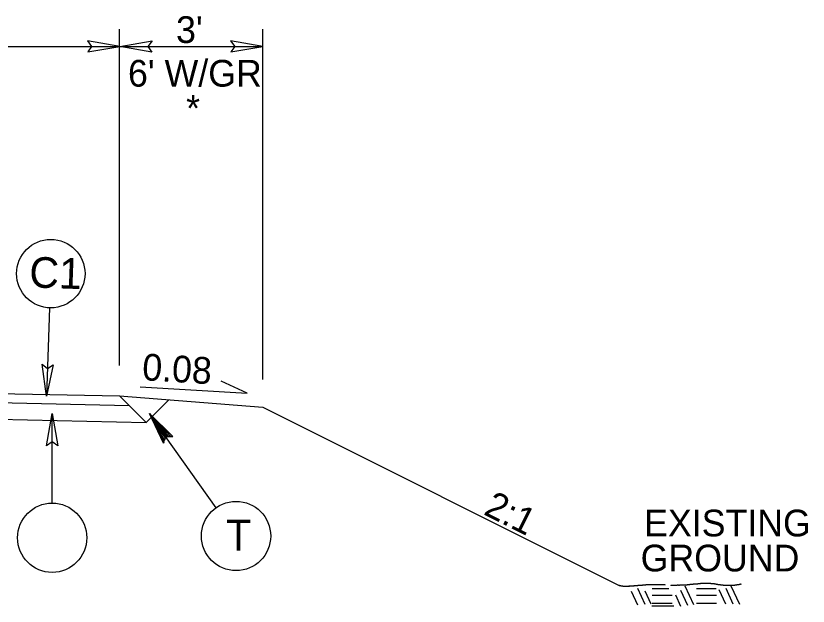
# Model space of a CAD drawing. Extents: x 1542177 to 1542464, y 45134 to 45344.
# Drawn here: x 1542284.79 to 1542302.59, y 45263.84 to 45277.09 of the extents above; entities that cross this region are included whole.
import ezdxf

# ---------------------------------------------------------------- set-up
doc = ezdxf.new("R2010")
doc.units = 0
for name, color, linetype in [('Default', 7, 'Continuous'), ('Typical Detail Wedge3 CELL', 7, 'Continuous'), ('Typical ID Circle CELL', 7, 'Continuous'), ('Typical Terminator CELL', 7, 'Continuous'), ('Typical Text ID Circle CELL', 7, 'Continuous')]:
    doc.layers.add(name, color=color, linetype=linetype)

# ---------------------------------------------------------------- blocks, each defined once
blk = doc.blocks.new('CIR2')
at = {"layer": 'Default'}
blk.add_line((0, -1.914), (0, 0), dxfattribs=at)
blk.add_lwpolyline([(-0.118, -0.686), (0, 0), (0.122, -0.69), (0, -0.602)], close=True, dxfattribs=at)
blk.add_circle((0, -2.655), 0.741, dxfattribs=at)

msp = doc.modelspace()

# ---------------------------------------------------------------- linework, layer by layer
at = {"layer": 'Default'}
for p, q in [((1542287.121, 45269.246), (1542287.121, 45276.797)), ((1542290.34, 45268.927), (1542290.34, 45276.797)), ((1542277.52, 45276.408), (1542287.12, 45276.408)), ((1542287.12, 45276.408), (1542290.34, 45276.408)), ((1542289.984, 45268.625), (1542289.402, 45268.893)), ((1542277.52, 45268.762), (1542287.12, 45268.562)), ((1542287.58, 45268.769), (1542289.984, 45268.625)), ((1542277.516, 45268.554), (1542287.333, 45268.35)), ((1542287.716, 45267.967), (1542287.12, 45268.562)), ((1542287.12, 45268.562), (1542290.34, 45268.306)), ((1542287.716, 45267.967), (1542288.224, 45268.474)), ((1542290.34, 45268.306), (1542298.347, 45264.303)), ((1542277.52, 45268.179), (1542287.716, 45267.967)), ((1542298.614, 45264.179), (1542298.755, 45263.875)), ((1542298.752, 45264.243), (1542298.917, 45263.888)), ((1542298.92, 45264.184), (1542299.054, 45263.895)), ((1542299.462, 45264.231), (1542299.085, 45264.231)), ((1542299.724, 45264.199), (1542299.881, 45263.861)), ((1542299.819, 45264.298), (1542300.016, 45263.876)), ((1542300.526, 45264.231), (1542300.079, 45264.231)), ((1542300.582, 45264.214), (1542300.73, 45263.895)), ((1542300.736, 45264.245), (1542300.9, 45263.896)), ((1542300.853, 45264.3), (1542301.044, 45263.887)), ((1542299.536, 45264.08), (1542299.085, 45264.079)), ((1542299.606, 45264.093), (1542299.721, 45263.842)), ((1542300.527, 45264.079), (1542300.079, 45264.079)), ((1542299.572, 45263.843), (1542299.077, 45263.843)), ((1542299.535, 45263.903), (1542299.087, 45263.904)), ((1542300.527, 45263.905), (1542300.079, 45263.905))]:
    msp.add_line(p, q, dxfattribs=at)
for points in [[(1542286.405, 45276.285), (1542287.125, 45276.409), (1542286.401, 45276.537), (1542286.493, 45276.409)], [(1542287.847, 45276.282), (1542287.127, 45276.406), (1542287.851, 45276.534), (1542287.759, 45276.406)], [(1542289.62, 45276.284), (1542290.34, 45276.408), (1542289.616, 45276.536), (1542289.708, 45276.408)]]:
    msp.add_lwpolyline(points, close=True, dxfattribs=at)
msp.add_lwpolyline([(1542287.12, 45268.562), (1542287.333, 45268.35)], dxfattribs=at)
for points in [[(1542301.083, 45264.329), (1542301.083, 45264.33), (1542301.082, 45264.331), (1542301.081, 45264.332), (1542301.079, 45264.333), (1542301.076, 45264.332), (1542301.074, 45264.332), (1542301.072, 45264.332), (1542301.069, 45264.333), (1542301.066, 45264.332), (1542301.064, 45264.332), (1542301.062, 45264.33), (1542301.06, 45264.33), (1542301.058, 45264.329), (1542301.055, 45264.328), (1542301.053, 45264.328), (1542301.05, 45264.327), (1542301.048, 45264.327), (1542301.045, 45264.326), (1542301.043, 45264.326), (1542301.041, 45264.325), (1542301.039, 45264.324), (1542301.036, 45264.324), (1542301.033, 45264.325), (1542301.031, 45264.325), (1542301.028, 45264.324), (1542301.026, 45264.323), (1542301.023, 45264.323), (1542301.021, 45264.322), (1542301.019, 45264.324), (1542301.016, 45264.323), (1542301.014, 45264.322), (1542301.011, 45264.322), (1542301.008, 45264.321), (1542301.006, 45264.32), (1542301.004, 45264.319), (1542301.002, 45264.319), (1542300.999, 45264.318), (1542300.997, 45264.318), (1542300.994, 45264.318), (1542300.992, 45264.318), (1542300.989, 45264.318), (1542300.987, 45264.317), (1542300.985, 45264.317), (1542300.983, 45264.316), (1542300.98, 45264.316), (1542300.978, 45264.315), (1542300.975, 45264.314), (1542300.973, 45264.314), (1542300.97, 45264.313), (1542300.968, 45264.314), (1542300.966, 45264.314), (1542300.963, 45264.313), (1542300.961, 45264.312), (1542300.958, 45264.312), (1542300.956, 45264.311), (1542300.954, 45264.311), (1542300.952, 45264.31), (1542300.948, 45264.31), (1542300.945, 45264.311), (1542300.942, 45264.31), (1542300.939, 45264.31), (1542300.937, 45264.308), (1542300.935, 45264.308), (1542300.931, 45264.308), (1542300.927, 45264.308), (1542300.924, 45264.308), (1542300.921, 45264.308), (1542300.919, 45264.309), (1542300.917, 45264.309), (1542300.913, 45264.308), (1542300.91, 45264.308), (1542300.906, 45264.307), (1542300.904, 45264.307), (1542300.902, 45264.306), (1542300.899, 45264.306), (1542300.896, 45264.306), (1542300.893, 45264.307), (1542300.889, 45264.307), (1542300.886, 45264.307), (1542300.884, 45264.307), (1542300.881, 45264.307), (1542300.877, 45264.307), (1542300.874, 45264.306), (1542300.87, 45264.306), (1542300.866, 45264.306), (1542300.863, 45264.306), (1542300.86, 45264.306), (1542300.857, 45264.306), (1542300.854, 45264.307), (1542300.852, 45264.307), (1542300.85, 45264.307), (1542300.847, 45264.306), (1542300.845, 45264.306), (1542300.842, 45264.306), (1542300.838, 45264.307), (1542300.835, 45264.307), (1542300.831, 45264.307), (1542300.827, 45264.307), (1542300.823, 45264.307), (1542300.821, 45264.307), (1542300.819, 45264.306), (1542300.817, 45264.306), (1542300.813, 45264.306), (1542300.81, 45264.307), (1542300.806, 45264.307), (1542300.803, 45264.307), (1542300.801, 45264.307), (1542300.798, 45264.307), (1542300.795, 45264.307), (1542300.793, 45264.306), (1542300.791, 45264.306), (1542300.789, 45264.306), (1542300.787, 45264.306), (1542300.785, 45264.306), (1542300.782, 45264.306), (1542300.78, 45264.306), (1542300.778, 45264.306), (1542300.776, 45264.306), (1542300.773, 45264.306), (1542300.771, 45264.306), (1542300.768, 45264.306), (1542300.766, 45264.306), (1542300.763, 45264.306), (1542300.761, 45264.306), (1542300.758, 45264.306), (1542300.755, 45264.306), (1542300.753, 45264.306), (1542300.751, 45264.306), (1542300.749, 45264.306), (1542300.747, 45264.306), (1542300.745, 45264.306), (1542300.743, 45264.306), (1542300.739, 45264.306), (1542300.735, 45264.306), (1542300.731, 45264.306), (1542300.728, 45264.306), (1542300.726, 45264.306), (1542300.723, 45264.306), (1542300.722, 45264.306), (1542300.72, 45264.306), (1542300.718, 45264.306), (1542300.714, 45264.306), (1542300.71, 45264.308), (1542300.706, 45264.308), (1542300.704, 45264.309), (1542300.701, 45264.309), (1542300.699, 45264.309), (1542300.696, 45264.309), (1542300.692, 45264.308), (1542300.689, 45264.308), (1542300.685, 45264.308), (1542300.681, 45264.31), (1542300.677, 45264.311), (1542300.673, 45264.311), (1542300.67, 45264.31), (1542300.667, 45264.31), (1542300.663, 45264.31), (1542300.659, 45264.311), (1542300.656, 45264.312), (1542300.652, 45264.312), (1542300.649, 45264.313), (1542300.646, 45264.314), (1542300.642, 45264.314), (1542300.638, 45264.314), (1542300.635, 45264.314), (1542300.632, 45264.314), (1542300.63, 45264.315), (1542300.628, 45264.315), (1542300.625, 45264.316), (1542300.623, 45264.317), (1542300.621, 45264.317), (1542300.617, 45264.318), (1542300.613, 45264.317), (1542300.609, 45264.317), (1542300.606, 45264.318), (1542300.604, 45264.318), (1542300.602, 45264.319), (1542300.599, 45264.319), (1542300.597, 45264.32), (1542300.595, 45264.32), (1542300.592, 45264.321), (1542300.59, 45264.321), (1542300.588, 45264.321), (1542300.583, 45264.321), (1542300.577, 45264.321), (1542300.571, 45264.322), (1542300.569, 45264.323), (1542300.566, 45264.324), (1542300.563, 45264.324), (1542300.561, 45264.325), (1542300.558, 45264.326), (1542300.556, 45264.326), (1542300.554, 45264.327), (1542300.551, 45264.326), (1542300.549, 45264.326), (1542300.545, 45264.326), (1542300.542, 45264.329), (1542300.538, 45264.329), (1542300.536, 45264.33), (1542300.533, 45264.329), (1542300.53, 45264.33), (1542300.527, 45264.33), (1542300.524, 45264.333), (1542300.521, 45264.334), (1542300.518, 45264.334), (1542300.516, 45264.333), (1542300.513, 45264.333), (1542300.511, 45264.334), (1542300.509, 45264.334), (1542300.507, 45264.335), (1542300.504, 45264.336), (1542300.502, 45264.337), (1542300.499, 45264.337), (1542300.497, 45264.338), (1542300.494, 45264.338), (1542300.491, 45264.339), (1542300.488, 45264.339), (1542300.484, 45264.34), (1542300.481, 45264.34), (1542300.478, 45264.34), (1542300.476, 45264.34), (1542300.474, 45264.34), (1542300.472, 45264.34), (1542300.47, 45264.342), (1542300.468, 45264.342), (1542300.465, 45264.342), (1542300.462, 45264.342), (1542300.459, 45264.342), (1542300.457, 45264.342), (1542300.455, 45264.342), (1542300.452, 45264.342), (1542300.449, 45264.342), (1542300.445, 45264.343), (1542300.442, 45264.344), (1542300.439, 45264.344), (1542300.436, 45264.344), (1542300.434, 45264.344), (1542300.432, 45264.344), (1542300.43, 45264.346), (1542300.428, 45264.346), (1542300.424, 45264.346), (1542300.42, 45264.345), (1542300.416, 45264.345), (1542300.414, 45264.345), (1542300.412, 45264.346), (1542300.409, 45264.346), (1542300.407, 45264.346), (1542300.405, 45264.347), (1542300.403, 45264.347), (1542300.401, 45264.347), (1542300.398, 45264.347), (1542300.395, 45264.347), (1542300.393, 45264.347), (1542300.391, 45264.347), (1542300.389, 45264.347), (1542300.386, 45264.347), (1542300.384, 45264.347), (1542300.382, 45264.347), (1542300.38, 45264.348), (1542300.377, 45264.347), (1542300.375, 45264.347), (1542300.372, 45264.347), (1542300.37, 45264.349), (1542300.367, 45264.349), (1542300.365, 45264.349), (1542300.362, 45264.349), (1542300.36, 45264.349), (1542300.358, 45264.349), (1542300.355, 45264.349), (1542300.352, 45264.349), (1542300.35, 45264.349), (1542300.349, 45264.349), (1542300.347, 45264.349), (1542300.343, 45264.349), (1542300.338, 45264.349), (1542300.334, 45264.349), (1542300.33, 45264.349), (1542300.325, 45264.349), (1542300.321, 45264.349), (1542300.319, 45264.349), (1542300.316, 45264.349), (1542300.313, 45264.349), (1542300.306, 45264.348), (1542300.299, 45264.35), (1542300.292, 45264.349), (1542300.29, 45264.349), (1542300.288, 45264.349), (1542300.286, 45264.349), (1542300.283, 45264.349), (1542300.281, 45264.349), (1542300.278, 45264.349), (1542300.276, 45264.349), (1542300.274, 45264.349), (1542300.271, 45264.349), (1542300.269, 45264.349), (1542300.266, 45264.349), (1542300.264, 45264.349), (1542300.26, 45264.349), (1542300.256, 45264.349), (1542300.253, 45264.349), (1542300.25, 45264.349), (1542300.247, 45264.349), (1542300.245, 45264.349), (1542300.243, 45264.349), (1542300.24, 45264.349), (1542300.238, 45264.349), (1542300.236, 45264.349), (1542300.233, 45264.349), (1542300.231, 45264.349), (1542300.229, 45264.349), (1542300.226, 45264.349), (1542300.224, 45264.349), (1542300.222, 45264.349), (1542300.219, 45264.348), (1542300.217, 45264.348), (1542300.215, 45264.348), (1542300.212, 45264.349), (1542300.21, 45264.349), (1542300.208, 45264.349), (1542300.206, 45264.349), (1542300.204, 45264.349), (1542300.2, 45264.349), (1542300.197, 45264.348), (1542300.193, 45264.348), (1542300.19, 45264.348), (1542300.188, 45264.348), (1542300.185, 45264.348), (1542300.183, 45264.348), (1542300.18, 45264.347), (1542300.178, 45264.347), (1542300.176, 45264.347), (1542300.174, 45264.348), (1542300.171, 45264.348), (1542300.169, 45264.348), (1542300.167, 45264.345), (1542300.164, 45264.345), (1542300.162, 45264.345), (1542300.159, 45264.346), (1542300.157, 45264.346), (1542300.154, 45264.346), (1542300.152, 45264.346), (1542300.149, 45264.346), (1542300.146, 45264.346), (1542300.142, 45264.345), (1542300.138, 45264.345), (1542300.136, 45264.345), (1542300.133, 45264.344), (1542300.131, 45264.343), (1542300.129, 45264.343), (1542300.127, 45264.344), (1542300.125, 45264.343), (1542300.122, 45264.343), (1542300.12, 45264.342), (1542300.117, 45264.342), (1542300.102, 45264.339), (1542300.087, 45264.338), (1542300.071, 45264.337), (1542300.069, 45264.336), (1542300.067, 45264.337), (1542300.064, 45264.337), (1542300.062, 45264.336), (1542300.059, 45264.335), (1542300.056, 45264.334), (1542300.055, 45264.334), (1542300.053, 45264.334), (1542300.051, 45264.334), (1542300.048, 45264.334), (1542300.045, 45264.335), (1542300.043, 45264.335), (1542300.04, 45264.335), (1542300.038, 45264.333), (1542300.036, 45264.333), (1542300.033, 45264.333), (1542300.031, 45264.333), (1542300.029, 45264.333), (1542300.023, 45264.333), (1542300.017, 45264.333), (1542300.011, 45264.333), (1542300.008, 45264.333), (1542300.006, 45264.332), (1542300.003, 45264.331), (1542300.001, 45264.331), (1542299.998, 45264.331), (1542299.996, 45264.331), (1542299.993, 45264.331), (1542299.991, 45264.329), (1542299.988, 45264.329), (1542299.98, 45264.328), (1542299.972, 45264.328), (1542299.964, 45264.328), (1542299.957, 45264.327), (1542299.951, 45264.327), (1542299.944, 45264.326), (1542299.94, 45264.326), (1542299.936, 45264.325), (1542299.933, 45264.324), (1542299.929, 45264.324), (1542299.925, 45264.323), (1542299.921, 45264.322), (1542299.919, 45264.322), (1542299.916, 45264.323), (1542299.914, 45264.322), (1542299.911, 45264.322), (1542299.909, 45264.32), (1542299.907, 45264.32), (1542299.905, 45264.32), (1542299.902, 45264.321), (1542299.9, 45264.32), (1542299.898, 45264.32), (1542299.895, 45264.319), (1542299.893, 45264.319), (1542299.889, 45264.319), (1542299.886, 45264.319), (1542299.882, 45264.318), (1542299.88, 45264.318), (1542299.877, 45264.318), (1542299.874, 45264.317), (1542299.872, 45264.317), (1542299.869, 45264.317), (1542299.866, 45264.317), (1542299.861, 45264.316), (1542299.855, 45264.317), (1542299.849, 45264.317), (1542299.846, 45264.317), (1542299.842, 45264.315), (1542299.838, 45264.315), (1542299.836, 45264.315), (1542299.834, 45264.315), (1542299.831, 45264.315), (1542299.826, 45264.315), (1542299.82, 45264.315), (1542299.815, 45264.315), (1542299.812, 45264.315), (1542299.81, 45264.315), (1542299.808, 45264.315), (1542299.805, 45264.314), (1542299.803, 45264.313), (1542299.801, 45264.313), (1542299.798, 45264.313), (1542299.796, 45264.313), (1542299.793, 45264.313), (1542299.787, 45264.313), (1542299.781, 45264.313), (1542299.775, 45264.313), (1542299.773, 45264.313), (1542299.77, 45264.313), (1542299.768, 45264.313), (1542299.765, 45264.313), (1542299.763, 45264.311), (1542299.76, 45264.311), (1542299.758, 45264.311), (1542299.755, 45264.311), (1542299.753, 45264.311), (1542299.747, 45264.311), (1542299.741, 45264.311), (1542299.735, 45264.311), (1542299.733, 45264.311), (1542299.731, 45264.311), (1542299.729, 45264.311), (1542299.726, 45264.311), (1542299.723, 45264.311), (1542299.72, 45264.311), (1542299.715, 45264.311), (1542299.709, 45264.31), (1542299.704, 45264.31), (1542299.702, 45264.31), (1542299.7, 45264.31), (1542299.698, 45264.31), (1542299.693, 45264.309), (1542299.688, 45264.309), (1542299.683, 45264.309), (1542299.68, 45264.309), (1542299.677, 45264.31), (1542299.675, 45264.31), (1542299.669, 45264.31), (1542299.663, 45264.31), (1542299.657, 45264.31), (1542299.648, 45264.31), (1542299.64, 45264.309), (1542299.631, 45264.309), (1542299.625, 45264.309), (1542299.619, 45264.307), (1542299.613, 45264.307), (1542299.611, 45264.307), (1542299.61, 45264.308), (1542299.608, 45264.308), (1542299.605, 45264.308), (1542299.603, 45264.308), (1542299.6, 45264.308), (1542299.594, 45264.308), (1542299.588, 45264.308), (1542299.582, 45264.308), (1542299.579, 45264.308), (1542299.577, 45264.308), (1542299.575, 45264.308), (1542299.573, 45264.308), (1542299.571, 45264.306), (1542299.568, 45264.306), (1542299.566, 45264.305), (1542299.563, 45264.305), (1542299.56, 45264.305), (1542299.558, 45264.305), (1542299.556, 45264.305), (1542299.554, 45264.305), (1542299.552, 45264.306), (1542299.549, 45264.306), (1542299.547, 45264.305), (1542299.544, 45264.305), (1542299.542, 45264.304), (1542299.54, 45264.304), (1542299.537, 45264.304), (1542299.534, 45264.304), (1542299.531, 45264.304), (1542299.529, 45264.304), (1542299.527, 45264.305), (1542299.524, 45264.305), (1542299.522, 45264.305), (1542299.52, 45264.304), (1542299.518, 45264.304), (1542299.515, 45264.304), (1542299.512, 45264.304), (1542299.51, 45264.304), (1542299.508, 45264.304), (1542299.506, 45264.302), (1542299.503, 45264.302), (1542299.503, 45264.302), (1542299.503, 45264.302), (1542299.503, 45264.302)], [(1542299.379, 45264.317), (1542299.376, 45264.317), (1542299.374, 45264.318), (1542299.371, 45264.318), (1542299.365, 45264.319), (1542299.36, 45264.318), (1542299.354, 45264.318), (1542299.352, 45264.319), (1542299.35, 45264.32), (1542299.347, 45264.32), (1542299.341, 45264.32), (1542299.335, 45264.32), (1542299.329, 45264.32), (1542299.321, 45264.32), (1542299.312, 45264.32), (1542299.304, 45264.32), (1542299.298, 45264.32), (1542299.292, 45264.322), (1542299.286, 45264.322), (1542299.28, 45264.322), (1542299.274, 45264.321), (1542299.268, 45264.321), (1542299.266, 45264.322), (1542299.264, 45264.322), (1542299.261, 45264.322), (1542299.256, 45264.322), (1542299.25, 45264.322), (1542299.244, 45264.322), (1542299.242, 45264.322), (1542299.239, 45264.322), (1542299.237, 45264.322), (1542299.231, 45264.322), (1542299.224, 45264.322), (1542299.218, 45264.321), (1542299.216, 45264.321), (1542299.213, 45264.321), (1542299.211, 45264.321), (1542299.208, 45264.321), (1542299.206, 45264.321), (1542299.203, 45264.321), (1542299.198, 45264.321), (1542299.192, 45264.321), (1542299.187, 45264.321), (1542299.181, 45264.321), (1542299.175, 45264.321), (1542299.169, 45264.321), (1542299.165, 45264.322), (1542299.162, 45264.322), (1542299.158, 45264.322), (1542299.153, 45264.322), (1542299.148, 45264.321), (1542299.143, 45264.321), (1542299.141, 45264.321), (1542299.138, 45264.322), (1542299.136, 45264.322), (1542299.134, 45264.322), (1542299.132, 45264.322), (1542299.129, 45264.321), (1542299.127, 45264.321), (1542299.124, 45264.321), (1542299.121, 45264.321), (1542299.119, 45264.321), (1542299.117, 45264.322), (1542299.115, 45264.322), (1542299.111, 45264.322), (1542299.107, 45264.322), (1542299.104, 45264.322), (1542299.101, 45264.322), (1542299.099, 45264.322), (1542299.097, 45264.322), (1542299.094, 45264.322), (1542299.092, 45264.322), (1542299.089, 45264.322), (1542299.087, 45264.322), (1542299.085, 45264.321), (1542299.083, 45264.321), (1542299.081, 45264.321), (1542299.078, 45264.321), (1542299.076, 45264.321), (1542299.074, 45264.321), (1542299.073, 45264.321), (1542299.071, 45264.321), (1542299.068, 45264.321), (1542299.065, 45264.321), (1542299.063, 45264.321), (1542299.06, 45264.321), (1542299.058, 45264.321), (1542299.055, 45264.321), (1542299.052, 45264.321), (1542299.049, 45264.322), (1542299.046, 45264.322), (1542299.043, 45264.322), (1542299.04, 45264.322), (1542299.036, 45264.322), (1542299.031, 45264.322), (1542299.026, 45264.321), (1542299.021, 45264.321), (1542299.019, 45264.321), (1542299.017, 45264.321), (1542299.015, 45264.321), (1542299.012, 45264.321), (1542299.01, 45264.319), (1542299.008, 45264.319), (1542299.005, 45264.319), (1542299.003, 45264.32), (1542299.001, 45264.32), (1542298.993, 45264.319), (1542298.984, 45264.318), (1542298.976, 45264.318), (1542298.97, 45264.318), (1542298.964, 45264.318), (1542298.958, 45264.318), (1542298.956, 45264.318), (1542298.954, 45264.318), (1542298.951, 45264.318), (1542298.949, 45264.318), (1542298.946, 45264.317), (1542298.944, 45264.317), (1542298.941, 45264.316), (1542298.939, 45264.315), (1542298.936, 45264.314), (1542298.934, 45264.314), (1542298.932, 45264.314), (1542298.93, 45264.314), (1542298.927, 45264.314), (1542298.925, 45264.313), (1542298.922, 45264.312), (1542298.916, 45264.312), (1542298.91, 45264.313), (1542298.904, 45264.312), (1542298.901, 45264.312), (1542298.897, 45264.31), (1542298.894, 45264.31), (1542298.891, 45264.31), (1542298.888, 45264.31), (1542298.885, 45264.31), (1542298.882, 45264.31), (1542298.879, 45264.311), (1542298.875, 45264.311), (1542298.873, 45264.311), (1542298.871, 45264.31), (1542298.869, 45264.309), (1542298.864, 45264.309), (1542298.859, 45264.309), (1542298.854, 45264.308), (1542298.852, 45264.308), (1542298.849, 45264.307), (1542298.847, 45264.307), (1542298.845, 45264.307), (1542298.842, 45264.307), (1542298.84, 45264.307), (1542298.838, 45264.307), (1542298.836, 45264.307), (1542298.834, 45264.307), (1542298.828, 45264.307), (1542298.822, 45264.307), (1542298.816, 45264.307), (1542298.814, 45264.307), (1542298.811, 45264.306), (1542298.808, 45264.306), (1542298.806, 45264.306), (1542298.803, 45264.305), (1542298.801, 45264.305), (1542298.798, 45264.305), (1542298.796, 45264.305), (1542298.793, 45264.305), (1542298.791, 45264.305), (1542298.789, 45264.303), (1542298.786, 45264.303), (1542298.784, 45264.303), (1542298.782, 45264.303), (1542298.78, 45264.303), (1542298.777, 45264.304), (1542298.775, 45264.304), (1542298.772, 45264.304), (1542298.77, 45264.304), (1542298.767, 45264.304), (1542298.765, 45264.304), (1542298.762, 45264.303), (1542298.76, 45264.302), (1542298.758, 45264.302), (1542298.756, 45264.302), (1542298.754, 45264.302), (1542298.752, 45264.302), (1542298.749, 45264.302), (1542298.746, 45264.302), (1542298.744, 45264.302), (1542298.741, 45264.302), (1542298.739, 45264.3), (1542298.737, 45264.3), (1542298.733, 45264.3), (1542298.73, 45264.3), (1542298.726, 45264.3), (1542298.724, 45264.299), (1542298.721, 45264.299), (1542298.719, 45264.298), (1542298.716, 45264.298), (1542298.712, 45264.299), (1542298.708, 45264.299), (1542298.706, 45264.298), (1542298.704, 45264.297), (1542298.702, 45264.297), (1542298.698, 45264.296), (1542298.695, 45264.295), (1542298.691, 45264.295), (1542298.687, 45264.294), (1542298.684, 45264.295), (1542298.68, 45264.295), (1542298.678, 45264.295), (1542298.675, 45264.295), (1542298.672, 45264.295), (1542298.664, 45264.294), (1542298.656, 45264.293), (1542298.648, 45264.293), (1542298.644, 45264.292), (1542298.641, 45264.293), (1542298.637, 45264.292), (1542298.635, 45264.292), (1542298.632, 45264.291), (1542298.629, 45264.291), (1542298.627, 45264.291), (1542298.625, 45264.291), (1542298.623, 45264.291), (1542298.62, 45264.291), (1542298.618, 45264.291), (1542298.615, 45264.291), (1542298.611, 45264.291), (1542298.608, 45264.29), (1542298.604, 45264.29), (1542298.602, 45264.29), (1542298.6, 45264.29), (1542298.598, 45264.29), (1542298.595, 45264.289), (1542298.593, 45264.289), (1542298.59, 45264.289), (1542298.587, 45264.289), (1542298.583, 45264.288), (1542298.58, 45264.288), (1542298.578, 45264.287), (1542298.575, 45264.287), (1542298.573, 45264.287), (1542298.57, 45264.287), (1542298.567, 45264.288), (1542298.565, 45264.288), (1542298.561, 45264.288), (1542298.558, 45264.285), (1542298.555, 45264.285), (1542298.552, 45264.285), (1542298.55, 45264.285), (1542298.547, 45264.285), (1542298.545, 45264.286), (1542298.542, 45264.286), (1542298.54, 45264.286), (1542298.53, 45264.286), (1542298.521, 45264.284), (1542298.512, 45264.284), (1542298.506, 45264.284), (1542298.5, 45264.284), (1542298.494, 45264.284), (1542298.492, 45264.284), (1542298.489, 45264.284), (1542298.487, 45264.284), (1542298.485, 45264.284), (1542298.482, 45264.284), (1542298.48, 45264.284), (1542298.474, 45264.284), (1542298.468, 45264.283), (1542298.462, 45264.283), (1542298.46, 45264.283), (1542298.458, 45264.285), (1542298.456, 45264.285), (1542298.449, 45264.285), (1542298.443, 45264.285), (1542298.436, 45264.285), (1542298.434, 45264.285), (1542298.432, 45264.285), (1542298.43, 45264.285), (1542298.427, 45264.285), (1542298.425, 45264.288), (1542298.423, 45264.288), (1542298.417, 45264.289), (1542298.411, 45264.287), (1542298.405, 45264.288), (1542298.403, 45264.288), (1542298.401, 45264.289), (1542298.399, 45264.289), (1542298.396, 45264.29), (1542298.394, 45264.29), (1542298.391, 45264.291), (1542298.389, 45264.292), (1542298.386, 45264.292), (1542298.384, 45264.293), (1542298.38, 45264.294), (1542298.376, 45264.296), (1542298.372, 45264.297), (1542298.37, 45264.297), (1542298.367, 45264.296), (1542298.364, 45264.297), (1542298.362, 45264.297), (1542298.36, 45264.298), (1542298.358, 45264.299), (1542298.355, 45264.3), (1542298.353, 45264.301), (1542298.351, 45264.302), (1542298.35, 45264.302), (1542298.348, 45264.303), (1542298.347, 45264.303)]]:
    msp.add_open_spline(points, degree=3, dxfattribs=at)
at = {"layer": 'Typical Detail Wedge3 CELL'}
msp.add_lwpolyline([(1542288.106, 45267.504), (1542288.156, 45267.654), (1542288.315, 45267.652), (1542287.795, 45268.164), (1542288.27, 45267.652), (1542288.224, 45267.654), (1542287.795, 45268.164), (1542288.18, 45267.654), (1542288.156, 45267.654), (1542287.795, 45268.164), (1542288.143, 45267.612), (1542288.129, 45267.569), (1542287.795, 45268.164), (1542288.114, 45267.526), (1542288.106, 45267.504), (1542287.795, 45268.164)], dxfattribs=at)
at = {"layer": 'Typical ID Circle CELL'}
for p, q in [((1542285.55, 45270.54), (1542285.48, 45268.553)), ((1542289.289, 45266.052), (1542288.156, 45267.654))]:
    msp.add_line(p, q, dxfattribs=at)
for centre, radius in [((1542285.576, 45271.308), 0.769), ((1542289.738, 45265.417), 0.778)]:
    msp.add_circle(centre, radius, dxfattribs=at)
at = {"layer": 'Typical Terminator CELL'}
msp.add_lwpolyline([(1542285.628, 45269.26), (1542285.48, 45268.553), (1542285.379, 45269.273), (1542285.502, 45269.177)], close=True, dxfattribs=at)

# ---------------------------------------------------------------- block references
at = {"layer": 'Default', "xscale": 1.0498642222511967, "yscale": 1.0498642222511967}
msp.add_blockref('CIR2', (1542285.607, 45268.165), dxfattribs=at)

# ---------------------------------------------------------------- texts
at = {"layer": 'Default'}
for s, p in [("3'", (1542288.39, 45276.485)), ("6' W/GR", (1542287.31, 45275.505)), ('*', (1542288.617, 45274.719)), ('EXISTING', (1542298.904, 45265.408)), ('GROUND', (1542298.826, 45264.622))]:
    msp.add_text(s, height=0.6, dxfattribs=at).set_placement(p)
for s, rotation, p in [('0.08', 356.5617, (1542287.617, 45268.917)), ('2:1', 333.4349, (1542295.275, 45265.913))]:
    msp.add_text(s, height=0.6, rotation=rotation, dxfattribs=at).set_placement(p)
at = {"layer": 'Typical Text ID Circle CELL'}
msp.add_text('C1', height=0.6886, rotation=358, dxfattribs=at).set_placement((1542285.085, 45271))
msp.add_text('T', height=0.696, dxfattribs=at).set_placement((1542289.51, 45265.089))

doc.saveas('drawing.dxf')
